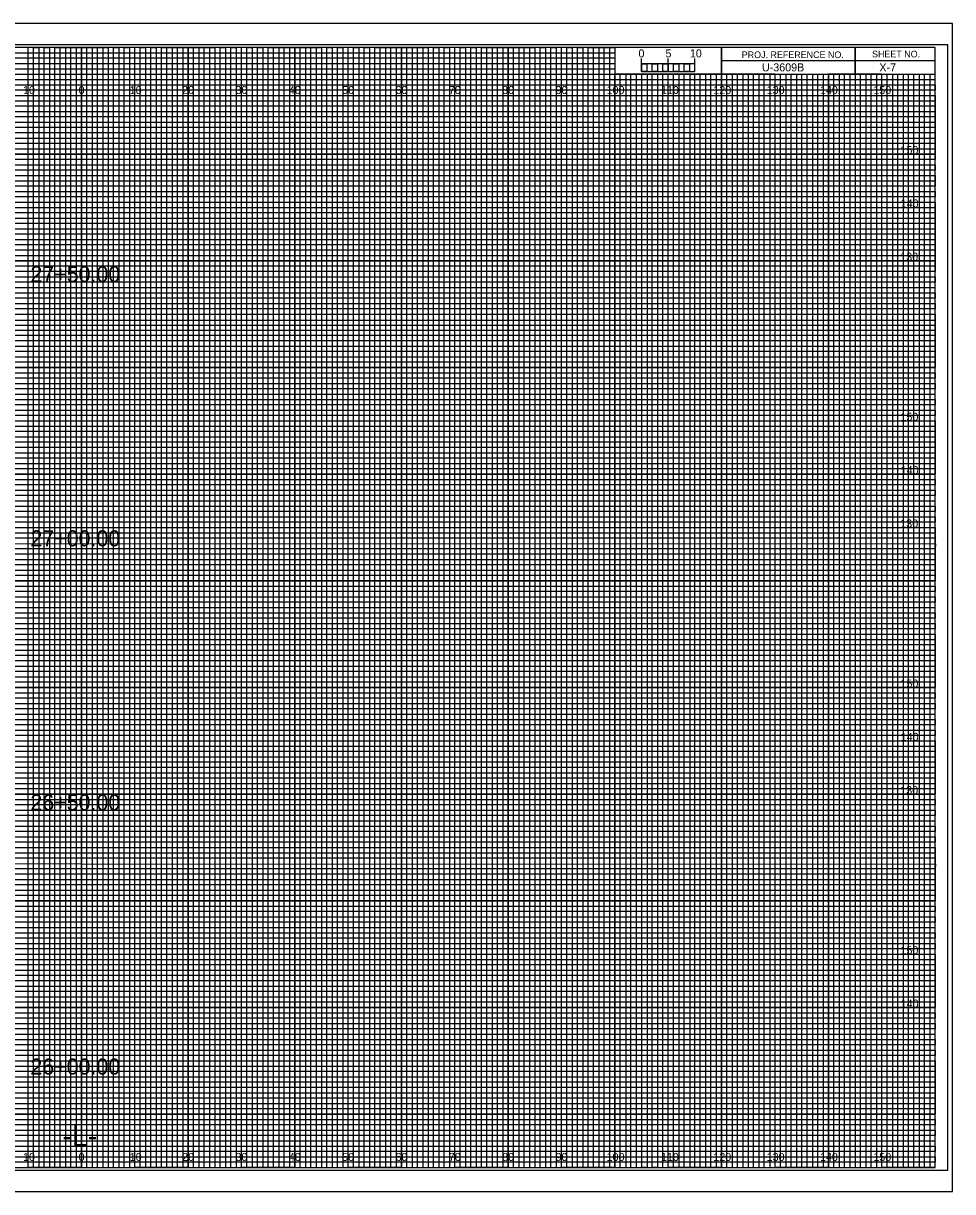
# Model space of a CAD drawing. Extents: x -13 to 329, y -17 to 10994.
# Drawn here: x 149.1 to 323.3, y 1095.5 to 1314.5 of the extents above; entities that cross this region are included whole.
import ezdxf

# ---------------------------------------------------------------- set-up
doc = ezdxf.new("R2010")
doc.units = 0
for name, color, linetype in [('Prop XS Alignment Label', 7, 'Continuous'), ('Prop XS Bar Scale Labels', 7, 'Continuous'), ('Prop XS Elevation Labels', 7, 'Continuous'), ('Prop XS Offset Labels', 7, 'Continuous'), ('Prop XS Project Number', 7, 'Continuous'), ('Prop XS Sheet Number', 7, 'Continuous'), ('Prop XS Station Labels', 7, 'Continuous'), ('Sheet Cross Section CELL', 7, 'Continuous'), ('Sheet Cross Section Grid Major CELL', 7, 'Continuous'), ('Sheet Cross Section Grid Middle CELL', 7, 'Continuous'), ('Sheet Cross Section Grid Minor 1 CELL', 7, 'Continuous'), ('Sheet Cross Section Grid Minor 2 CELL', 7, 'Continuous'), ('Sheet Cross Section Scale CELL', 7, 'Continuous'), ('Sheet Cutting Line CELL', 7, 'Continuous'), ('Sheet DOT Grid CELL', 7, 'Continuous'), ('Sheet Plot Border Inside CELL', 7, 'Continuous'), ('Sheet Plot Border Outside CELL', 7, 'Continuous')]:
    doc.layers.add(name, color=color, linetype=linetype)

msp = doc.modelspace()

# ---------------------------------------------------------------- linework, layer by layer
at = {"layer": 'Sheet Cross Section CELL'}
for p, q in [((305, 1310), (305, 1305)), ((305, 1305), (305, 1310)), ((280, 1307.5), (280, 1305)), ((320, 1307.49), (280, 1307.49)), ((280, 1305), (320, 1305))]:
    msp.add_line(p, q, dxfattribs=at)
for points in [[(320, 1310), (0, 1310), (0, 1100), (320, 1100)], [(280, 1310), (260, 1310), (260, 1305.03), (280, 1305.03)], [(320, 1310), (280, 1310), (280, 1305), (320, 1305)]]:
    msp.add_lwpolyline(points, close=True, dxfattribs=at)
at = {"layer": 'Sheet Cross Section Grid Major CELL'}
for p, q in [((150, 1310), (140, 1310)), ((150, 1100), (150, 1310)), ((170, 1310), (160, 1310)), ((160, 1310), (160, 1100)), ((170, 1100), (170, 1310)), ((190, 1310), (180, 1310)), ((180, 1310), (180, 1100)), ((190, 1100), (190, 1310)), ((210, 1310), (200, 1310)), ((200, 1310), (200, 1100)), ((210, 1100), (210, 1310)), ((230, 1310), (220, 1310)), ((220, 1310), (220, 1100)), ((230, 1100), (230, 1310)), ((250, 1310), (240, 1310)), ((240, 1310), (240, 1100)), ((250, 1100), (250, 1310)), ((260, 1310), (260, 1100)), ((270, 1100), (270, 1305)), ((290, 1305), (280, 1305)), ((280, 1305), (280, 1100)), ((290, 1100), (290, 1305)), ((310, 1305), (300, 1305)), ((300, 1305), (300, 1100)), ((310, 1100), (310, 1305)), ((160, 1100), (150, 1100)), ((180, 1100), (170, 1100)), ((200, 1100), (190, 1100)), ((220, 1100), (210, 1100)), ((240, 1100), (230, 1100)), ((260, 1100), (250, 1100)), ((280, 1100), (270, 1100)), ((300, 1100), (290, 1100)), ((320, 1100), (310, 1100)), ((320, 1100), (320, 1100))]:
    msp.add_line(p, q, dxfattribs=at)
for points in [[(0, 1300), (320, 1300), (320, 1290), (0, 1290)], [(0, 1280), (320, 1280), (320, 1270), (0, 1270)], [(0, 1260), (320, 1260), (320, 1250), (0, 1250)], [(0, 1240), (320, 1240), (320, 1230), (0, 1230)], [(0, 1220), (320, 1220), (320, 1210), (0, 1210)], [(0, 1200), (320, 1200), (320, 1190), (0, 1190)], [(0, 1180), (320, 1180), (320, 1170), (0, 1170)], [(0, 1160), (320, 1160), (320, 1150), (0, 1150)], [(0, 1140), (320, 1140), (320, 1130), (0, 1130)], [(0, 1120), (320, 1120), (320, 1110), (0, 1110)]]:
    msp.add_lwpolyline(points, dxfattribs=at)
at = {"layer": 'Sheet Cross Section Grid Middle CELL'}
for points in [[(145, 1100), (155, 1100), (155, 1310), (165, 1310), (165, 1100), (175, 1100), (175, 1310), (185, 1310), (185, 1100), (195, 1100), (195, 1310), (205, 1310), (205, 1100), (215, 1100), (215, 1310), (225, 1310), (225, 1100), (235, 1100), (235, 1310), (245, 1310), (245, 1100), (255, 1100), (255, 1310), (259.93, 1310), (260, 1310), (260, 1305), (264.99, 1305), (264.99, 1100), (275, 1100), (275, 1305), (285, 1305), (285, 1100), (295, 1100), (295, 1305), (305, 1305), (305, 1100), (315, 1100), (315, 1305)], [(0, 1305), (275, 1305)], [(0, 1285), (320, 1285), (320, 1295), (0, 1295)], [(0, 1265), (320, 1265), (320, 1275), (0, 1275)], [(0, 1245), (320, 1245), (320, 1255), (0, 1255)], [(0, 1225), (320, 1225), (320, 1235), (0, 1235)], [(0, 1205), (320, 1205), (320, 1215), (0, 1215)], [(0, 1185), (320, 1185), (320, 1195), (0, 1195)], [(0, 1165), (320, 1165), (320, 1175), (0, 1175)], [(0, 1145), (320, 1145), (320, 1155), (0, 1155)], [(0, 1125), (320, 1125), (320, 1135), (0, 1135)], [(0, 1105), (320, 1105), (320, 1115), (0, 1115)]]:
    msp.add_lwpolyline(points, dxfattribs=at)
at = {"layer": 'Sheet Cross Section Grid Minor 1 CELL'}
for p, q in [((0, 1309), (260, 1309)), ((260, 1307.98), (0, 1307.98)), ((260, 1309), (260, 1307.98)), ((0, 1307), (260, 1307)), ((260, 1305.89), (0, 1305.89)), ((260, 1307), (260, 1305.89)), ((0, 1304), (320, 1304))]:
    msp.add_line(p, q, dxfattribs=at)
for points in [[(0, 1303), (270, 1303), (320, 1303), (320, 1302), (0, 1302)], [(0, 1301), (320, 1301), (320, 1299), (0, 1299)], [(0, 1298), (320, 1298), (320, 1297), (0, 1296.98)], [(0, 1296), (320, 1296), (320, 1294), (0, 1294)], [(0, 1293), (320, 1293), (320, 1292), (0, 1292)], [(0, 1291), (320, 1291), (320, 1289), (0, 1289)], [(0, 1288), (320, 1288), (320, 1287), (0, 1287)], [(0, 1286), (320, 1286), (320, 1284), (0, 1284)], [(0, 1283), (320, 1283), (320, 1282), (0, 1282)], [(0, 1281), (320, 1281), (320, 1279), (0, 1279)], [(0, 1278), (320, 1278), (320, 1277), (0, 1277)], [(0, 1276), (320, 1276), (320, 1273.95), (320, 1273), (320, 1272), (0, 1272)], [(0, 1274), (320, 1274), (320, 1273), (0, 1273)], [(0, 1271), (320, 1271), (320, 1269), (0, 1269.03)], [(0, 1269.03), (320, 1269), (320, 1268), (0, 1268)], [(0, 1267), (320, 1267), (320, 1266), (0, 1266)], [(0, 1264), (320, 1264), (320, 1263), (0, 1263)], [(0, 1262), (320, 1262), (320, 1261), (0, 1261)], [(-0.07, 1258.89), (320, 1258.89), (320, 1257.88), (-0.07, 1257.88)], [(0, 1257), (320, 1257), (320, 1256), (0, 1256)], [(0, 1254), (320, 1254), (320, 1253), (0, 1253)], [(0, 1252), (320, 1252), (320, 1251), (0, 1251)], [(0, 1249), (320, 1249), (320, 1248), (0, 1248)], [(0, 1247), (320, 1247), (320, 1246), (0, 1246)], [(0, 1244), (320, 1244), (320, 1243), (0, 1243)], [(0, 1242), (320, 1242), (320, 1241), (0, 1241)], [(0, 1239), (320, 1239), (319.99, 1237.98), (0, 1238)], [(0, 1237), (320, 1237), (320, 1236), (0, 1236)], [(0, 1234), (320, 1234), (320, 1233), (0, 1233)], [(0, 1232), (320, 1232), (320, 1231), (0, 1231)], [(0, 1229), (320, 1229), (320, 1228), (0, 1228)], [(0, 1227), (320, 1227), (320, 1226), (0, 1226)], [(0, 1224), (320, 1224), (320, 1223), (0, 1223)], [(0, 1222), (320, 1222), (320, 1221), (0, 1221)], [(0, 1219), (320, 1219), (320, 1218), (0, 1218)], [(0, 1216.99), (320.07, 1216.91), (320, 1216), (0, 1216)], [(0, 1214), (320, 1214), (320, 1213), (0, 1213)], [(0, 1212), (320, 1212), (320, 1211), (0, 1211)], [(0, 1209), (320, 1209), (320, 1208), (0, 1208)], [(0, 1207), (320, 1207), (320, 1206), (0, 1206)], [(0, 1204), (320, 1204), (320, 1203), (0, 1203)], [(0, 1202), (320, 1202), (320, 1201), (0, 1201)], [(0, 1199), (320, 1199), (320, 1198), (0, 1198)], [(0, 1197), (320, 1197), (320, 1196), (0, 1196)], [(0, 1194), (320, 1194), (320, 1193), (0, 1193)], [(0, 1192), (320, 1192), (320, 1191), (0, 1191)], [(0, 1189), (320, 1189), (320, 1188), (0, 1188)], [(0, 1187), (320, 1187), (320, 1186), (0, 1186)], [(0, 1184), (320, 1184), (320, 1183), (0, 1183)], [(0, 1182), (320, 1182), (320, 1181), (0, 1181)], [(0, 1179), (320, 1179), (319.99, 1177.98), (0, 1178)], [(0, 1177), (320, 1177), (320, 1176), (0, 1176)], [(0, 1174), (320, 1174), (320, 1173), (0, 1173)], [(0, 1172), (320, 1172), (320, 1171), (0, 1171)], [(0, 1169), (320, 1169), (320, 1168), (0, 1168)], [(0, 1167), (320, 1167), (320, 1166), (0, 1166)], [(0, 1164), (320, 1164), (320, 1163), (0, 1163)], [(0, 1162), (320, 1162), (320, 1161), (0, 1161)], [(0, 1159), (320, 1159), (320, 1158), (0, 1158)], [(0, 1156.99), (320.07, 1156.91), (320, 1156), (0, 1156)], [(0, 1154), (320, 1154), (320, 1153), (0, 1153)], [(0, 1152), (320, 1152), (320, 1151), (0, 1151)], [(0, 1149), (320, 1149), (320, 1148), (0, 1148)], [(0, 1147), (320, 1147), (320, 1146), (0, 1146)], [(0, 1144), (320, 1144), (320, 1143), (0, 1143)], [(0, 1142), (320, 1142), (320, 1141), (0, 1141)], [(0, 1139), (320, 1139), (320, 1138), (0, 1138)], [(0, 1137), (320, 1137), (320, 1136), (0, 1136)], [(0, 1134), (320, 1134), (320, 1133), (0, 1133)], [(0, 1132), (320, 1132), (320, 1131), (0, 1131)], [(0, 1129), (320, 1129), (320, 1128), (0, 1128)], [(0, 1127), (320, 1127), (320, 1126), (0, 1126)], [(0, 1124), (320, 1124), (320, 1123), (0, 1123)], [(0, 1122), (320, 1122), (320, 1121), (0, 1121)], [(0, 1119), (320, 1119), (320, 1118), (0, 1118)], [(0, 1117), (320, 1117), (320, 1116), (0, 1116)], [(0, 1114), (320, 1114), (320, 1113), (0, 1113)], [(0, 1112), (320, 1112), (320, 1111), (0, 1111)], [(0, 1109), (320, 1109), (320, 1108), (0, 1108)], [(0, 1107), (320, 1107), (320, 1106), (0, 1106)], [(0, 1104), (320, 1104), (320, 1103), (0, 1103)], [(0, 1102), (320, 1102), (320, 1101), (0, 1101)]]:
    msp.add_lwpolyline(points, dxfattribs=at)
at = {"layer": 'Sheet Cross Section Grid Minor 2 CELL'}
for p, q in [((267, 1305), (266.01, 1305)), ((266.01, 1305), (266.01, 1100)), ((267, 1100), (267, 1305)), ((269, 1305), (268, 1305)), ((268, 1305), (268, 1100)), ((269, 1100), (269, 1305)), ((266.01, 1100), (265, 1100)), ((268, 1100), (267, 1100))]:
    msp.add_line(p, q, dxfattribs=at)
for points in [[(150, 1100), (151, 1100), (151, 1310), (152, 1310), (152, 1100)], [(152, 1100), (153, 1100), (153, 1310), (154, 1310), (154, 1100)], [(155, 1100), (156, 1100), (156, 1310), (157, 1310), (157, 1100)], [(157, 1100), (158, 1100), (158, 1310), (159, 1310), (159, 1100)], [(160, 1100), (161, 1100), (161, 1310), (162, 1310), (162, 1100)], [(162, 1100), (163, 1100), (163, 1310), (164, 1310), (164, 1100)], [(165, 1100), (166, 1100), (166, 1310), (167, 1310), (167, 1100)], [(167, 1100), (168, 1100), (168, 1310), (169, 1310), (169, 1100)], [(170, 1100), (171, 1100), (171, 1310), (172, 1310), (172, 1100)], [(172, 1100), (173, 1100), (173, 1310), (174, 1310), (174, 1100)], [(175, 1100), (176, 1100), (176, 1310), (177, 1310), (177, 1100)], [(177, 1100), (178, 1100), (178, 1310), (179, 1310), (179, 1100)], [(180, 1100), (181, 1100), (181, 1310), (182, 1310), (182, 1100)], [(182, 1100), (183, 1100), (183, 1310), (184, 1310), (184, 1100)], [(185, 1100), (186, 1100), (186, 1310), (187, 1310), (187, 1100)], [(187, 1100), (188, 1100), (188, 1310), (189, 1310), (189, 1100)], [(190, 1100), (191, 1100), (191, 1310), (192, 1310), (192, 1100)], [(192, 1100), (193, 1100), (193, 1310), (194, 1310), (194, 1100)], [(195, 1100), (196, 1100), (196, 1310), (197, 1310), (197, 1100)], [(197, 1100), (198, 1100), (198, 1310), (199, 1310), (199, 1100)], [(200, 1100), (201, 1100), (201, 1310), (202, 1310), (202, 1100)], [(202, 1100), (203, 1100), (203, 1310), (204, 1310), (204, 1100)], [(205, 1100), (206, 1100), (206, 1310), (207, 1310), (207, 1100)], [(207, 1100), (208, 1100), (208, 1310), (209, 1310), (209, 1100)], [(210, 1100), (211, 1100), (211, 1310), (212, 1310), (212, 1100)], [(212, 1100), (213, 1100), (213, 1310), (214, 1310), (214, 1100)], [(215, 1100), (216, 1100), (216, 1310), (217, 1310), (217, 1100)], [(217, 1100), (218, 1100), (218, 1310), (219, 1310), (219, 1100)], [(220, 1100), (221, 1100), (221, 1310), (222, 1310), (222, 1100)], [(222, 1100), (223, 1100), (223, 1310), (224, 1310), (224, 1100)], [(225, 1100), (226, 1100), (226, 1310), (227, 1310), (227, 1100)], [(227, 1100), (228, 1100), (228, 1310), (229, 1310), (229, 1100)], [(230, 1100), (231, 1100), (231, 1310), (232, 1310), (232, 1100)], [(232, 1100), (233, 1100), (233, 1310), (234, 1310), (234, 1100)], [(235, 1100), (236, 1100), (236, 1310), (237, 1310), (237, 1100)], [(237, 1100), (238, 1100), (238, 1310), (239, 1310), (239, 1100)], [(240, 1100), (241, 1100), (241, 1310), (242, 1310), (242, 1100)], [(242, 1100), (243, 1100), (243, 1310), (244, 1310), (244, 1100)], [(245, 1100), (246, 1100), (246, 1310), (247, 1310), (247, 1100)], [(247, 1100), (248, 1100), (248, 1310), (249, 1310), (249, 1100)], [(250, 1100), (251, 1100), (251, 1310), (252, 1310), (252, 1100)], [(252, 1100), (253, 1100), (253, 1310), (254, 1310), (254, 1100)], [(255, 1100), (256, 1100), (256, 1310), (257, 1310), (257, 1100)], [(257, 1100), (258, 1100), (258, 1310), (259, 1310), (259, 1100)], [(260, 1100), (261, 1100), (261, 1305), (262.02, 1305), (262.02, 1100)], [(262, 1100), (263, 1100), (263, 1305), (263.99, 1305), (263.99, 1100)], [(270, 1100), (270.98, 1100), (270.98, 1305), (272, 1305), (272, 1100)], [(272, 1100), (273, 1100), (273, 1305), (274.05, 1305), (274.05, 1100)], [(275, 1100), (276, 1100), (276, 1305), (277, 1305), (277, 1100)], [(277, 1100), (278, 1100), (278, 1305), (279, 1305), (279, 1100)], [(280, 1100), (281, 1100), (281, 1305), (282, 1305), (282, 1100)], [(282, 1100), (283, 1100), (283, 1305), (284, 1305), (284, 1100)], [(285, 1100), (286, 1100), (286, 1305), (287, 1305), (287, 1100)], [(287, 1100), (288, 1100), (288, 1305), (289, 1305), (289, 1100)], [(290, 1100), (291, 1100), (291, 1305), (292, 1305), (292, 1100)], [(292, 1100), (293, 1100), (293, 1305), (294, 1305), (294, 1100)], [(295, 1100), (296, 1100), (296, 1305), (297, 1305), (297, 1100)], [(297, 1100), (298, 1100), (298, 1305), (299, 1305), (299, 1100)], [(300, 1100), (301, 1100), (301, 1305), (302, 1305), (302, 1100)], [(302, 1100), (303, 1100), (303, 1305), (304, 1305), (304, 1100)], [(305, 1100), (306, 1100), (306, 1305), (307, 1305), (307, 1100)], [(307, 1100), (308, 1100), (308, 1305), (309, 1305), (309, 1100)], [(310, 1100), (311, 1100), (311, 1305), (312, 1305), (312, 1100)], [(312, 1100), (313, 1100), (313, 1305), (314, 1305), (314, 1100)], [(315, 1100), (316, 1100), (316, 1305), (317, 1305), (317, 1100)], [(317, 1100), (318, 1100), (318, 1305), (319, 1305), (319, 1100)]]:
    msp.add_lwpolyline(points, dxfattribs=at)
at = {"layer": 'Sheet Cross Section Scale CELL'}
for p, q in [((265, 1305.49), (265, 1307.9)), ((265, 1306.9), (265, 1307.9)), ((270, 1305.49), (270, 1307.9)), ((275, 1305.49), (275, 1307.9)), ((275, 1306.9), (275, 1307.9))]:
    msp.add_line(p, q, dxfattribs=at)
for points in [[(275, 1306.9), (265, 1306.9), (265, 1305.49), (275, 1305.49)], [(265, 1306.9), (266, 1306.9), (266, 1305.49), (265, 1305.49)], [(267, 1306.9), (268, 1306.9), (268, 1305.49), (267, 1305.49)], [(269, 1306.9), (270, 1306.9), (270, 1305.49), (269, 1305.49)], [(271, 1306.9), (272, 1306.9), (272, 1305.49), (271, 1305.49)], [(273, 1306.9), (274, 1306.9), (274, 1305.49), (273, 1305.49)]]:
    msp.add_lwpolyline(points, close=True, dxfattribs=at)
at = {"layer": 'Sheet Cutting Line CELL'}
for p, q in [((323.3, 1314.5), (-13.4, 1314.5)), ((-13.4, 1095.5), (323.3, 1095.5))]:
    msp.add_line(p, q, dxfattribs=at)
at = {"layer": 'Sheet DOT Grid CELL'}
for p, q in [((150, 1100), (150, 1310)), ((160, 1100), (160, 1310)), ((170, 1100), (170, 1310)), ((180, 1100), (180, 1310)), ((190, 1100), (190, 1310)), ((200, 1100), (200, 1310)), ((210, 1100), (210, 1310)), ((220, 1100), (220, 1310)), ((230, 1100), (230, 1310)), ((240, 1100), (240, 1310)), ((250, 1100), (250, 1310)), ((260, 1100), (260, 1304.69)), ((270, 1100), (270, 1304.69)), ((280, 1100), (280, 1304.69)), ((290, 1100), (290, 1304.69)), ((300, 1100), (300, 1304.69)), ((310, 1100), (310, 1304.69)), ((0, 1300), (320, 1300)), ((0, 1290), (320, 1290)), ((0, 1280), (320, 1280)), ((0, 1270), (320, 1270)), ((0, 1260), (320, 1260)), ((0, 1250), (320, 1250)), ((0, 1240), (320, 1240)), ((0, 1230), (320, 1230)), ((0, 1220), (320, 1220)), ((0, 1210), (320, 1210)), ((0, 1200), (320, 1200)), ((0, 1190), (320, 1190)), ((0, 1180), (320, 1180)), ((0, 1170), (320, 1170)), ((0, 1160), (320, 1160)), ((0, 1150), (320, 1150)), ((0, 1140), (320, 1140)), ((0, 1130), (320, 1130)), ((0, 1120), (320, 1120)), ((0, 1110), (320, 1110))]:
    msp.add_line(p, q, dxfattribs=at)
at = {"layer": 'Sheet Plot Border Inside CELL'}
msp.add_lwpolyline([(-10.8, 1099.5), (322.4, 1099.5), (322.4, 1310.5), (-10.8, 1310.5)], close=True, dxfattribs=at)
at = {"layer": 'Sheet Plot Border Outside CELL'}
msp.add_lwpolyline([(-13.4, 1095.5), (323.3, 1095.5), (323.3, 1314.5), (-13.4, 1314.5)], close=True, dxfattribs=at)

# ---------------------------------------------------------------- texts
at = {"layer": 'Prop XS Alignment Label'}
msp.add_text('-L-', height=4, dxfattribs=at).set_placement((156.42, 1104))
at = {"layer": 'Prop XS Bar Scale Labels'}
for s, p in [('5', (269.47, 1308.12)), ('10', (274.04, 1308.12))]:
    msp.add_text(s, height=1.5, dxfattribs=at).set_placement(p)
at = {"layer": 'Prop XS Elevation Labels'}
for s, p in [('150', (313.52, 1290)), ('140', (313.57, 1280)), ('130', (313.49, 1270)), ('150', (313.52, 1240)), ('140', (313.57, 1230)), ('130', (313.49, 1220)), ('150', (313.52, 1190)), ('140', (313.57, 1180)), ('130', (313.49, 1170)), ('150', (313.52, 1140)), ('140', (313.57, 1130))]:
    msp.add_text(s, height=1.5, dxfattribs=at).set_placement(p)
at = {"layer": 'Prop XS Offset Labels'}
for s, p in [('10', (149.04, 1301.25)), ('0', (159.45, 1301.25)), ('0', (159.45, 1301.25)), ('10', (169.04, 1301.25)), ('20', (178.86, 1301.25)), ('30', (188.86, 1301.25)), ('40', (198.86, 1301.25)), ('50', (208.86, 1301.25)), ('60', (218.86, 1301.25)), ('70', (228.86, 1301.25)), ('80', (238.86, 1301.25)), ('90', (248.86, 1301.25)), ('100', (258.44, 1301.25)), ('110', (268.62, 1301.25)), ('120', (278.44, 1301.25)), ('130', (288.44, 1301.25)), ('140', (298.44, 1301.25)), ('150', (308.44, 1301.25)), ('10', (149.04, 1101.25)), ('0', (159.45, 1101.25)), ('0', (159.45, 1101.25)), ('10', (169.04, 1101.25)), ('20', (178.86, 1101.25)), ('30', (188.86, 1101.25)), ('40', (198.86, 1101.25)), ('50', (208.86, 1101.25)), ('60', (218.86, 1101.25)), ('70', (228.86, 1101.25)), ('80', (238.86, 1101.25)), ('90', (248.86, 1101.25)), ('100', (258.44, 1101.25)), ('110', (268.62, 1101.25)), ('120', (278.44, 1101.25)), ('130', (288.44, 1101.25)), ('140', (298.44, 1101.25)), ('150', (308.44, 1101.25))]:
    msp.add_text(s, height=1.5, dxfattribs=at).set_placement(p)
at = {"layer": 'Prop XS Project Number'}
msp.add_text('U-3609B', height=1.5, dxfattribs=at).set_placement((287.56, 1305.5))
at = {"layer": 'Prop XS Sheet Number'}
msp.add_text('X-7', height=1.5, dxfattribs=at).set_placement((309.57, 1305.5))
at = {"layer": 'Prop XS Station Labels'}
for s, p in [('27+50.00', (150.41, 1265.99)), ('27+00.00', (150.41, 1216.47)), ('26+50.00', (150.41, 1166.97)), ('26+00.00', (150.41, 1117.45))]:
    msp.add_text(s, height=3, dxfattribs=at).set_placement(p)
at = {"layer": 'Sheet Cross Section CELL'}
for s, p in [('PROJ. REFERENCE NO.', (283.77, 1307.99)), ('SHEET NO.', (308.19, 1308.12))]:
    msp.add_text(s, height=1.25, dxfattribs=at).set_placement(p)
at = {"layer": 'Sheet Cross Section Scale CELL'}
msp.add_text('0', height=1.5, dxfattribs=at).set_placement((264.41, 1308.12))

doc.saveas('drawing.dxf')
